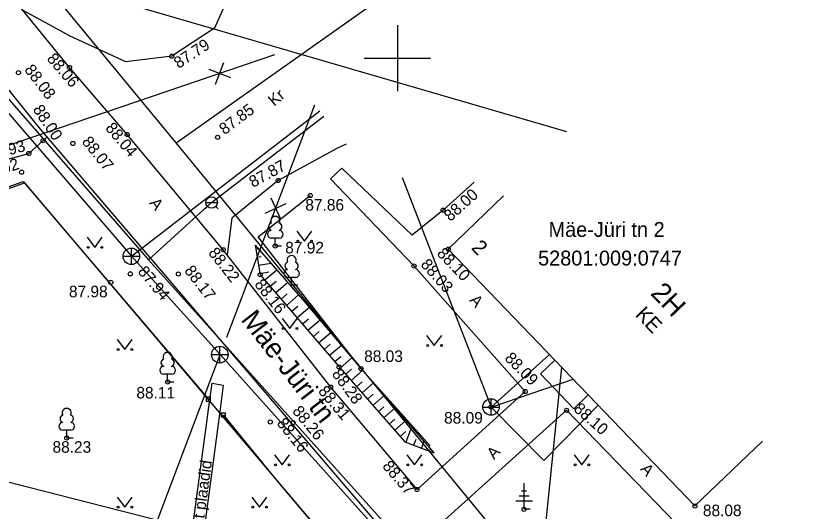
# Model space of a CAD drawing. Extents: x 648748 to 649126, y 6457789 to 6458252.
# Drawn here: x 648976.94 to 649025.8, y 6458022.55 to 6458052.54 of the extents above; entities that cross this region are included whole.
import ezdxf

# ---------------------------------------------------------------- set-up
doc = ezdxf.new("R2010")
doc.units = 0
for name, color, linetype in [('AED', 7, 'Continuous'), ('HALJASTUS', 7, 'Continuous'), ('HOONE', 7, 'Continuous'), ('KKAEV', 7, 'Continuous'), ('KORGUS-EH2000', 7, 'Continuous'), ('KTRASS', 7, 'Continuous'), ('MPOHULIIN', 7, 'Continuous'), ('PIIR', 7, 'Continuous'), ('PUU', 7, 'Continuous'), ('RELJEEF', 7, 'Continuous'), ('SIOHULIIN', 7, 'Continuous'), ('TEE', 7, 'Continuous'), ('VKAEV', 7, 'Continuous'), ('VORK', 7, 'Continuous'), ('VTRASS', 7, 'Continuous')]:
    doc.layers.add(name, color=color, linetype=linetype)

msp = doc.modelspace()

# ---------------------------------------------------------------- linework, layer by layer
at = {"layer": 'AED'}
for p, q in [((648988.429, 6458029.506), (648988.429, 6458029.256)), ((648988.429, 6458029.506), (648988.679, 6458029.506)), ((648988.429, 6458029.256), (648988.679, 6458029.256)), ((648988.679, 6458029.506), (648988.679, 6458029.256)), ((648989.34, 6458028.551), (648989.34, 6458028.301)), ((648989.34, 6458028.551), (648989.59, 6458028.551)), ((648989.34, 6458028.301), (648989.59, 6458028.301)), ((648989.59, 6458028.551), (648989.59, 6458028.301))]:
    msp.add_line(p, q, dxfattribs=at)
for points in [[(648972.029, 6458040.633), (648977.363, 6458042.54), (648988.554, 6458029.381)], [(648989.465, 6458028.426), (648992.661, 6458024.491), (648999.161, 6458016.792), (649000.589, 6458014.851), (649006.117, 6458000.931), (649011.441, 6457974.934)]]:
    msp.add_lwpolyline(points, dxfattribs=at)
at = {"layer": 'HALJASTUS'}
for p, q in [((648993.916, 6458039.532), (648994.38, 6458038.926)), ((648994.38, 6458038.926), (648994.825, 6458039.532)), ((648981.235, 6458039.158), (648981.699, 6458038.551)), ((648981.699, 6458038.551), (648982.144, 6458039.158)), ((648993.032, 6458034.249), (648993.496, 6458033.643)), ((648993.496, 6458033.643), (648993.941, 6458034.249)), ((649001.772, 6458033.22), (649002.235, 6458032.613)), ((649002.235, 6458032.613), (649002.681, 6458033.22)), ((648983.051, 6458032.981), (648983.514, 6458032.374)), ((648983.514, 6458032.374), (648983.96, 6458032.981)), ((648992.562, 6458026.007), (648993.026, 6458025.4)), ((648993.026, 6458025.4), (648993.471, 6458026.007)), ((649000.579, 6458026.007), (649001.043, 6458025.4)), ((649001.043, 6458025.4), (649001.488, 6458026.007)), ((649010.693, 6458026.007), (649011.157, 6458025.4)), ((649011.157, 6458025.4), (649011.602, 6458026.007)), ((648983.051, 6458023.442), (648983.514, 6458022.835)), ((648983.514, 6458022.835), (648983.96, 6458023.442)), ((648991.187, 6458023.442), (648991.651, 6458022.835)), ((648991.651, 6458022.835), (648992.096, 6458023.442))]:
    msp.add_line(p, q, dxfattribs=at)
msp.add_lwpolyline([(649001.981, 6458026.553), (648997.801, 6458031.212), (648991.587, 6458039.19), (648994.735, 6458041.686)], dxfattribs=at)
for centre in [(648993.979, 6458038.926), (648994.808, 6458038.926), (648981.298, 6458038.551), (648982.127, 6458038.551), (648993.095, 6458033.643), (648993.924, 6458033.643), (649001.834, 6458032.613), (649002.663, 6458032.613), (648983.113, 6458032.374), (648983.942, 6458032.374), (648992.625, 6458025.4), (648993.454, 6458025.4), (649000.642, 6458025.4), (649001.471, 6458025.4), (649010.756, 6458025.4), (649011.585, 6458025.4), (648983.113, 6458022.835), (648983.942, 6458022.835), (648991.25, 6458022.835), (648992.079, 6458022.835)]:
    msp.add_circle(centre, 0.055, dxfattribs=at)
at = {"layer": 'HOONE'}
for points in [[(649006.419, 6458041.672), (649003.079, 6458038.442), (649018, 6458022.906), (649022.091, 6458026.835)], [(649009.527, 6458031.729), (649008.657, 6458030.893), (649010.679, 6458028.787), (649011.549, 6458029.623)]]:
    msp.add_lwpolyline(points, dxfattribs=at)
at = {"layer": 'KKAEV'}
for p, q in [((648983.908, 6458037.511), (648983.908, 6458038.511)), ((648983.408, 6458038.011), (648984.408, 6458038.011)), ((648989.26, 6458031.564), (648989.26, 6458032.564)), ((648988.76, 6458032.064), (648989.76, 6458032.064)), ((649005.667, 6458028.393), (649005.667, 6458029.393)), ((649005.167, 6458028.893), (649006.167, 6458028.893))]:
    msp.add_line(p, q, dxfattribs=at)
for centre in [(648983.908, 6458038.011), (648989.26, 6458032.064), (649005.667, 6458028.893)]:
    msp.add_circle(centre, 0.5, dxfattribs=at)
at = {"layer": 'KORGUS-EH2000'}
for centre in [(648986.355, 6458050.114), (648977.08, 6458049.121), (648980.163, 6458049.435), (648983.655, 6458045.376), (648989.131, 6458045.206), (648978.572, 6458045.009), (648980.372, 6458044.837), (648977.711, 6458044.232), (648977.269, 6458043.096), (648992.791, 6458042.597), (648994.735, 6458041.686), (649002.764, 6458040.8), (648989.468, 6458038.405), (648992.612, 6458038.63), (649003.079, 6458038.442), (649001.007, 6458037.421), (648983.849, 6458036.946), (648986.755, 6458036.94), (648991.702, 6458036.899), (648982.664, 6458036.43), (648996.474, 6458031.318), (648997.801, 6458031.212), (648986.104, 6458030.403), (648995.967, 6458030.098), (649007.735, 6458029.828), (649005.667, 6458028.893), (649010.237, 6458028.696), (648992.311, 6458027.988), (648993.684, 6458027.948), (648980.001, 6458027.013), (649001.193, 6458023.903), (649018, 6458022.906), (649007.666, 6458022.705)]:
    msp.add_circle(centre, 0.125, dxfattribs=at)
at = {"layer": 'KTRASS'}
for p, q in [((648961.748, 6458063.747), (648983.908, 6458038.011)), ((648966.352, 6458041.309), (648992.594, 6458050.212)), ((648988.99, 6458048.424), (648989.501, 6458049.728)), ((648988.594, 6458049.332), (648989.897, 6458048.82)), ((648983.908, 6458038.011), (648995.305, 6458046.804)), ((649000.296, 6458042.771), (649005.667, 6458028.893)), ((648992.347, 6458041.547), (648992.921, 6458040.27)), ((648991.995, 6458040.622), (648993.272, 6458041.196)), ((648983.908, 6458038.011), (648989.278, 6458032.064)), ((648984.798, 6458020.252), (648989.278, 6458032.064)), ((648989.278, 6458032.064), (649019.745, 6457998.112)), ((649005.667, 6458028.893), (649009.199, 6458032.07)), ((649005.667, 6458028.893), (649010.632, 6458030.578))]:
    msp.add_line(p, q, dxfattribs=at)
for points in [[(648989.681, 6458033.125), (648995.011, 6458047.174)], [(649005.667, 6458028.893), (649008.87, 6458025.659), (649012.142, 6458029.006)]]:
    msp.add_lwpolyline(points, dxfattribs=at)
at = {"layer": 'MPOHULIIN'}
for q in [(649009.948, 6458031.29), (648966.776, 6458026.817)]:
    msp.add_line((649008.42, 6458016.198), q, dxfattribs=at)
at = {"layer": 'PIIR'}
for p, q in [((648986.62, 6458044.87), (649009.459, 6458061.03)), ((648986.62, 6458044.87), (648973.89, 6458060.32)), ((649022.96, 6458000.66), (648986.62, 6458044.87)), ((648963.88, 6458037.67), (648977.45, 6458042.46)), ((648977.45, 6458042.46), (649000.18, 6458015.64))]:
    msp.add_line(p, q, dxfattribs=at)
at = {"layer": 'PUU'}
for p, q in [((648992.852, 6458039.105), (648992.372, 6458039.105)), ((648992.612, 6458038.63), (648992.612, 6458039.105)), ((648992.992, 6458038.63), (648992.612, 6458038.63)), ((648993.841, 6458036.729), (648993.361, 6458036.729)), ((648993.601, 6458036.254), (648993.601, 6458036.729)), ((648993.981, 6458036.254), (648993.601, 6458036.254)), ((648986.344, 6458030.878), (648985.864, 6458030.878)), ((648986.104, 6458030.403), (648986.104, 6458030.878)), ((648986.484, 6458030.403), (648986.104, 6458030.403)), ((648980.241, 6458027.488), (648979.761, 6458027.488)), ((648980.001, 6458027.013), (648980.001, 6458027.488)), ((648980.381, 6458027.013), (648980.001, 6458027.013)), ((649007.666, 6458022.705), (649007.666, 6458024.28)), ((649007.966, 6458023.505), (649007.366, 6458023.505)), ((649007.816, 6458023.805), (649007.516, 6458023.805)), ((649008.166, 6458023.205), (649007.166, 6458023.205)), ((649008.026, 6458022.705), (649007.666, 6458022.705))]:
    msp.add_line(p, q, dxfattribs=at)
for centre, radius, start, end in [((648992.612, 6458040.15), 0.277, 332.58, 207.42), ((648992.442, 6458039.803), 0.233, 109.022, 253.142), ((648992.782, 6458039.803), 0.233, 286.851, 70.986), ((648992.375, 6458039.343), 0.238, 90.002, 269.395), ((648992.85, 6458039.343), 0.238, 270.605, 89.998), ((648993.601, 6458037.774), 0.277, 332.58, 207.42), ((648993.431, 6458037.427), 0.233, 109.022, 253.142), ((648993.771, 6458037.427), 0.233, 286.851, 70.986), ((648993.363, 6458036.967), 0.238, 90.002, 269.395), ((648993.838, 6458036.967), 0.238, 270.605, 89.998), ((648986.104, 6458031.923), 0.277, 332.58, 207.42), ((648985.934, 6458031.576), 0.233, 109.022, 253.142), ((648986.274, 6458031.576), 0.233, 286.851, 70.986), ((648985.867, 6458031.116), 0.238, 90.002, 269.395), ((648986.342, 6458031.116), 0.238, 270.605, 89.998), ((648980.001, 6458028.533), 0.277, 332.58, 207.42), ((648979.831, 6458028.185), 0.233, 109.022, 253.142), ((648980.171, 6458028.185), 0.233, 286.851, 70.986), ((648979.764, 6458027.725), 0.238, 90.002, 269.395), ((648980.239, 6458027.725), 0.238, 270.605, 89.998)]:
    msp.add_arc(centre, radius, start, end, dxfattribs=at)
at = {"layer": 'RELJEEF'}
for p, q in [((648991.593, 6458038.46), (648991.442, 6458038.434)), ((648991.752, 6458037.979), (648991.526, 6458037.941)), ((648992.364, 6458037.576), (648991.609, 6458037.448)), ((648992.221, 6458037.044), (648991.692, 6458036.955)), ((648992.71, 6458037.178), (648991.99, 6458036.562)), ((648992.677, 6458036.492), (648992.315, 6458036.182)), ((648993.368, 6458036.425), (648992.64, 6458035.802)), ((648993.331, 6458035.735), (648992.965, 6458035.422)), ((648994.025, 6458035.671), (648993.29, 6458035.042)), ((648993.984, 6458034.978), (648993.614, 6458034.662)), ((648994.677, 6458034.913), (648993.939, 6458034.282)), ((648994.632, 6458034.216), (648994.264, 6458033.902)), ((648995.322, 6458034.149), (648994.589, 6458033.522)), ((648995.279, 6458033.454), (648994.914, 6458033.142)), ((648995.967, 6458033.384), (648995.239, 6458032.762)), ((648995.927, 6458032.692), (648995.564, 6458032.382)), ((648996.612, 6458032.62), (648995.889, 6458032.002)), ((648996.574, 6458031.93), (648996.214, 6458031.622)), ((648997.25, 6458031.865), (648996.54, 6458031.243)), ((648997.221, 6458031.174), (648996.869, 6458030.866)), ((648997.896, 6458031.102), (648997.199, 6458030.49)), ((648997.876, 6458030.419), (648997.528, 6458030.114)), ((648998.551, 6458030.346), (648997.858, 6458029.738)), ((648998.533, 6458029.665), (648998.187, 6458029.362)), ((648999.207, 6458029.591), (648998.517, 6458028.986)), ((648999.19, 6458028.911), (648998.846, 6458028.61)), ((648999.862, 6458028.835), (648999.176, 6458028.234)), ((648999.847, 6458028.158), (648999.505, 6458027.858)), ((649000.517, 6458028.08), (648999.835, 6458027.482)), ((649000.504, 6458027.404), (649000.164, 6458027.106)), ((649000.861, 6458027.682), (649000.516, 6458026.761)), ((649001.109, 6458026.919), (649000.984, 6458026.585)), ((649001.607, 6458026.823), (649001.452, 6458026.41)), ((649001.95, 6458026.313), (649001.92, 6458026.234))]:
    msp.add_line(p, q, dxfattribs=at)
for points in [[(648991.4, 6458038.681), (648991.702, 6458036.899), (648996.474, 6458031.318), (649000.443, 6458026.789), (649002.213, 6458026.124)], [(648991.4, 6458038.681), (648994.404, 6458035.237), (648997.801, 6458031.212), (649002.213, 6458026.124)]]:
    msp.add_lwpolyline(points, dxfattribs=at)
at = {"layer": 'SIOHULIIN'}
msp.add_lwpolyline([(648981.628, 6458053.906), (649010.227, 6458045.558)], dxfattribs=at)
at = {"layer": 'TEE'}
for points in [[(649004.65, 6458042.504), (649002.764, 6458040.8), (649000.886, 6458039.29), (648996.637, 6458043.334), (648995.949, 6458042.696), (649001.007, 6458037.421), (649007.735, 6458029.828), (649001.193, 6458023.903), (648995.967, 6458030.098), (648989.468, 6458038.405), (648983.655, 6458045.376), (648980.163, 6458049.435), (648973.986, 6458057.003), (648970.576, 6458062.405), (648968.747, 6458067.645), (648969.273, 6458073.286), (648971.089, 6458082.764), (648972.682, 6458089.018), (648974.902, 6458101.691), (648976.958, 6458108.444), (648978.301, 6458112.451)], [(648949.689, 6457988.093), (648949.022, 6457989.19), (648951.214, 6457999.425), (648953.382, 6458008.934), (648954.806, 6458015.908), (648958.354, 6458027.992), (648959.727, 6458034.967), (648961.147, 6458039.663), (648962.725, 6458047.115), (648963.962, 6458052.11), (648965.802, 6458054.388), (648967.969, 6458055.624), (648969.67, 6458055.74), (648971.091, 6458054.761), (648978.388, 6458045.705), (649000.128, 6458020.255), (649018.273, 6457999), (649024.176, 6457993.684), (649043.03, 6457975.251)], [(648989.795, 6458053.731), (648988.932, 6458051.819), (648986.355, 6458050.114), (648983.579, 6458049.784), (648980.204, 6458051.329), (648977.359, 6458052.87)], [(648963.962, 6458052.11), (648963.419, 6458046.91), (648962.093, 6458040.76), (648962.04, 6458040.06), (648962.758, 6458039.601), (648964.965, 6458039.983), (648972.159, 6458042.733), (648977.711, 6458044.232)], [(648977.711, 6458044.232), (648978.803, 6458045.218)], [(648996.9, 6458044.8), (648996.369, 6458044.555), (648992.791, 6458042.597), (648989.982, 6458040.322), (648989.701, 6458038.107)], [(648984.734, 6458000.036), (648988.678, 6458029.486), (648988.793, 6458030.326), (648989.47, 6458030.22), (648989.281, 6458028.76), (648985.407, 6457999.812)], [(649073.892, 6457980.444), (649075.277, 6457978.898), (649074.998, 6457977.546), (649073.91, 6457975.39), (649075.219, 6457973.916), (649077.682, 6457970.841), (649078.634, 6457968.92), (649078.21, 6457966.199), (649076.118, 6457962.885), (649072.987, 6457959.848), (649068.76, 6457959.373), (649065.353, 6457959.385), (649062.208, 6457961.227), (649055.218, 6457967.101), (649039.374, 6457982.53), (649021.477, 6457999.638), (649003.487, 6458020.927), (649002.852, 6458022.042), (649010.237, 6458028.696), (649016.817, 6458021.893)]]:
    msp.add_lwpolyline(points, dxfattribs=at)
at = {"layer": 'VKAEV'}
for p, q in [((648988.519, 6458041.02), (648988.379, 6458040.88)), ((648988.416, 6458041.267), (648989.116, 6458041.267)), ((648989.014, 6458041.02), (648989.153, 6458040.88))]:
    msp.add_line(p, q, dxfattribs=at)
msp.add_circle((648988.766, 6458041.267), 0.35, dxfattribs=at)
at = {"layer": 'VORK'}
for p, q in [((649000, 6458052), (649000, 6458048)), ((648998, 6458050), (649002, 6458050))]:
    msp.add_line(p, q, dxfattribs=at)
at = {"layer": 'VTRASS'}
for points in [[(648962.245, 6458064.485), (648962.49, 6458064.476), (648963.533, 6458062.388), (648984.937, 6458037.806), (648985.682, 6458036.975), (649020.474, 6457998.164), (649045.944, 6457974.832), (649068.737, 6457953.518), (649069.454, 6457952.848), (649087.021, 6457962.34), (649109.829, 6457974.665)], [(648984.937, 6458037.806), (648988.766, 6458041.267), (648995.556, 6458046.489)]]:
    msp.add_lwpolyline(points, dxfattribs=at)

# ---------------------------------------------------------------- texts
at = {"layer": 'HOONE'}
for s, height, p in [('2', 0.9, (649004.427, 6458038.487)), ('2H', 1.2, (649015.264, 6458035.73)), ('KE', 0.9, (649014.343, 6458034.442))]:
    msp.add_text(s, height=height, rotation=313.8434, dxfattribs=at).set_placement(p)
at = {"layer": 'KORGUS-EH2000'}
for s, rotation, p in [('87.79', 33.4854, (648986.77, 6458049.338)), ('88.06', 310.7085, (648978.755, 6458049.938)), ('88.08', 307.5323, (648977.403, 6458049.288)), ('88.00', 303.4654, (648977.922, 6458046.898)), ('87.85', 37.136, (648989.548, 6458045.328)), ('88.04', 309.8242, (648982.296, 6458045.752)), ('87.93', 15.1098, (648975.287, 6458043.783)), ('88.07', 308.9497, (648980.877, 6458044.927)), ('87.92', 18.1597, (648974.96, 6458042.582)), ('87.87', 28.6921, (648991.266, 6458042.146)), ('88.00', 41.666, (649003.2, 6458040.083)), ('88.22', 308.0354, (648988.526, 6458038.209)), ('88.10', 313.8434, (649002.346, 6458038.138)), ('88.03', 311.5452, (649001.365, 6458037.489)), ('87.94', 310.2278, (648984.255, 6458037.064)), ('88.17', 307.6165, (648987.078, 6458037.136)), ('88.16', 308.0251, (648991.322, 6458036.301)), ('88.09', 314.6569, (649006.447, 6458031.797)), ('88.28', 306.1848, (648996.004, 6458030.888)), ('88.31', 310.1509, (648995.171, 6458029.827)), ('88.26', 309.5515, (648993.605, 6458028.625)), ('88.10', 318.3863, (649010.614, 6458028.706)), ('88.16', 308.7155, (648992.668, 6458027.9)), ('88.37', 310.7778, (648999.054, 6458025.288))]:
    msp.add_text(s, height=0.7, rotation=rotation, dxfattribs=at).set_placement(p)
for s, p in [('87.86', (648994.432, 6458040.772)), ('87.92', (648993.217, 6458038.184)), ('87.98', (648980.132, 6458035.53)), ('88.03', (648997.992, 6458031.62)), ('88.11', (648984.213, 6458029.41)), ('88.09', (649002.826, 6458027.891)), ('88.23', (648979.138, 6458026.126)), ('88.08', (649018.481, 6458022.289))]:
    msp.add_text(s, height=0.7, dxfattribs=at).set_placement(p)
at = {"layer": 'PIIR'}
for s, p in [('Mäe-Jüri tn 2', (649009.145, 6458039.183)), ('52801:009:0747', (649008.513, 6458037.453))]:
    msp.add_text(s, height=0.9, rotation=360, dxfattribs=at).set_placement(p)
at = {"layer": 'TEE'}
for s, height, rotation, p in [('Kr', 0.7, 40.0862, (648992.542, 6458047.056)), ('A', 0.7, 307.6165, (648984.971, 6458041.22)), ('A', 0.7, 311.1242, (649004.322, 6458035.33)), ('Mäe-Jüri tn', 1.2, 307.677, (648990.496, 6458034.17)), ('A', 0.7, 47.6178, (649005.851, 6458025.684)), ('bet plaadid', 0.7, 82.3776, (648988.182, 6458021.089)), ('A', 0.7, 311.1242, (649014.659, 6458025.116))]:
    msp.add_text(s, height=height, rotation=rotation, dxfattribs=at).set_placement(p)

doc.saveas('drawing.dxf')
